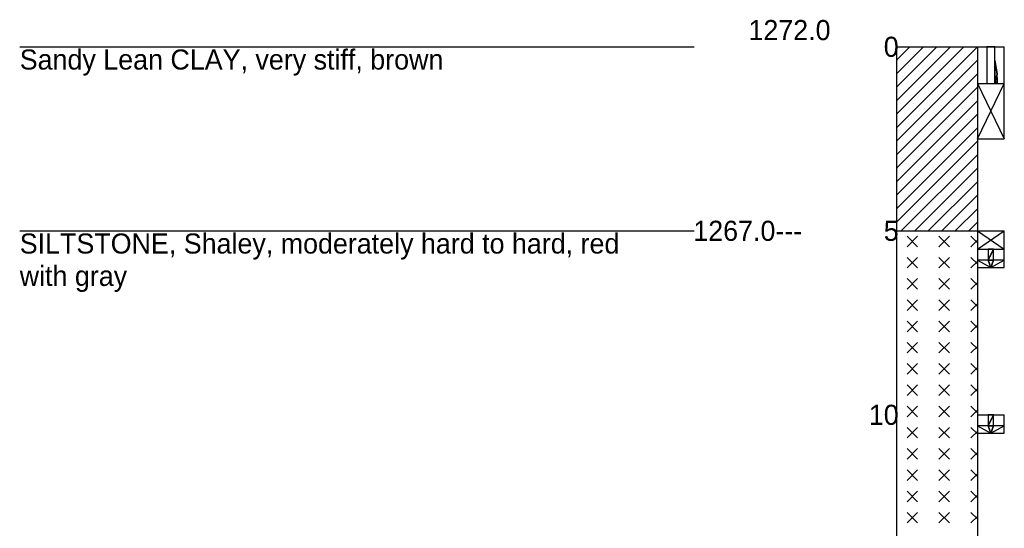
# Model space of a CAD drawing. Extents: x 2150161.5 to 2150203.1, y 143779.5 to 143868.5.
# Drawn here: x 2150186.76 to 2150192.84, y 143852.47 to 143855.61 of the extents above; entities that cross this region are included whole.
import ezdxf

# ---------------------------------------------------------------- set-up
doc = ezdxf.new("R2010")
doc.units = 0
doc.layers.add('Default', color=7, linetype='Continuous')

# ---------------------------------------------------------------- blocks, each defined once
blk = doc.blocks.new('POINT_DISPLAY')
at = {"layer": 'Default'}
blk.add_line((0, 0), (0, 0), dxfattribs=at)

msp = doc.modelspace()

# ---------------------------------------------------------------- linework, layer by layer
at = {"layer": 'Default'}
for points in [[(2150186.7605, 143855.4435), (2150190.9272, 143855.4435)], [(2150192.1772, 143855.3602), (2150192.2605, 143855.4435)], [(2150192.1772, 143855.2768), (2150192.3438, 143855.4435)], [(2150192.1772, 143855.1935), (2150192.4272, 143855.4435)], [(2150192.1772, 143855.1102), (2150192.5105, 143855.4435)], [(2150192.1772, 143855.0268), (2150192.5938, 143855.4435)], [(2150192.1772, 143854.9435), (2150192.6772, 143855.4435)], [(2150192.1772, 143855.4435), (2150192.1772, 143843.2844)], [(2150192.1772, 143855.4435), (2150192.6772, 143855.4435)], [(2150192.6772, 143855.4435), (2150192.8438, 143855.4435)], [(2150192.6772, 143855.4435), (2150192.6772, 143843.2844)], [(2150192.8438, 143855.2162), (2150192.8438, 143855.4435)], [(2150192.1772, 143854.8602), (2150192.6772, 143855.3602)], [(2150192.1772, 143854.7768), (2150192.6772, 143855.2768)], [(2150192.1772, 143854.6935), (2150192.6772, 143855.1935)], [(2150192.6772, 143855.2162), (2150192.8438, 143855.2162)], [(2150192.6772, 143855.2162), (2150192.8438, 143854.8753)], [(2150192.6772, 143854.8753), (2150192.8438, 143855.2162)], [(2150192.6772, 143855.2162), (2150192.8438, 143855.2162)], [(2150192.8438, 143854.8753), (2150192.8438, 143855.2162)], [(2150192.1772, 143854.6102), (2150192.6772, 143855.1102)], [(2150192.1772, 143854.5268), (2150192.6772, 143855.0268)], [(2150192.1772, 143854.4435), (2150192.6772, 143854.9435)], [(2150192.1772, 143854.3602), (2150192.6772, 143854.8602)], [(2150192.6772, 143854.8753), (2150192.8438, 143854.8753)], [(2150192.2075, 143854.3071), (2150192.6772, 143854.7768)], [(2150192.2908, 143854.3071), (2150192.6772, 143854.6935)], [(2150192.3741, 143854.3071), (2150192.6772, 143854.6102)], [(2150192.4575, 143854.3071), (2150192.6772, 143854.5268)], [(2150192.5408, 143854.3071), (2150192.6772, 143854.4435)], [(2150192.6241, 143854.3071), (2150192.6772, 143854.3602)], [(2150186.7605, 143854.3071), (2150190.9272, 143854.3071)], [(2150192.1772, 143854.3071), (2150192.6772, 143854.3071)], [(2150192.3084, 143854.2743), (2150192.2428, 143854.2087)], [(2150192.2428, 143854.2743), (2150192.3084, 143854.2087)], [(2150192.5053, 143854.2743), (2150192.4396, 143854.2087)], [(2150192.4396, 143854.2743), (2150192.5053, 143854.2087)], [(2150192.6365, 143854.2743), (2150192.6772, 143854.2337)], [(2150192.6772, 143854.3071), (2150192.8438, 143854.1935)], [(2150192.6772, 143854.1935), (2150192.8438, 143854.3071)], [(2150192.6772, 143854.3071), (2150192.8438, 143854.3071)], [(2150192.8438, 143854.1935), (2150192.8438, 143854.3071)], [(2150192.6772, 143854.2494), (2150192.6365, 143854.2087)], [(2150192.6772, 143854.1935), (2150192.8438, 143854.1935)], [(2150192.6772, 143854.1935), (2150192.8438, 143854.1935)], [(2150192.8438, 143854.0799), (2150192.8438, 143854.1935)], [(2150192.3084, 143854.1431), (2150192.2428, 143854.0775)], [(2150192.2428, 143854.1431), (2150192.3084, 143854.0775)], [(2150192.5053, 143854.1431), (2150192.4396, 143854.0775)], [(2150192.4396, 143854.1431), (2150192.5053, 143854.0775)], [(2150192.6365, 143854.1431), (2150192.6772, 143854.1024)], [(2150192.6772, 143854.1182), (2150192.6365, 143854.0775)], [(2150192.6772, 143854.0799), (2150192.8438, 143854.0799)], [(2150192.3084, 143854.0119), (2150192.2428, 143853.9463)], [(2150192.2428, 143854.0119), (2150192.3084, 143853.9463)], [(2150192.5053, 143854.0119), (2150192.4396, 143853.9463)], [(2150192.4396, 143854.0119), (2150192.5053, 143853.9463)], [(2150192.6365, 143854.0119), (2150192.6772, 143853.9712)], [(2150192.6772, 143853.9869), (2150192.6365, 143853.9463)], [(2150192.3084, 143853.8806), (2150192.2428, 143853.815)], [(2150192.2428, 143853.8806), (2150192.3084, 143853.815)], [(2150192.5053, 143853.8806), (2150192.4396, 143853.815)], [(2150192.4396, 143853.8806), (2150192.5053, 143853.815)], [(2150192.6365, 143853.8806), (2150192.6772, 143853.84)], [(2150192.6772, 143853.8557), (2150192.6365, 143853.815)], [(2150192.3084, 143853.7494), (2150192.2428, 143853.6838)], [(2150192.2428, 143853.7494), (2150192.3084, 143853.6838)], [(2150192.5053, 143853.7494), (2150192.4396, 143853.6838)], [(2150192.4396, 143853.7494), (2150192.5053, 143853.6838)], [(2150192.6365, 143853.7494), (2150192.6772, 143853.7087)], [(2150192.6772, 143853.7245), (2150192.6365, 143853.6838)], [(2150192.3084, 143853.6182), (2150192.2428, 143853.5526)], [(2150192.2428, 143853.6182), (2150192.3084, 143853.5526)], [(2150192.5053, 143853.6182), (2150192.4396, 143853.5526)], [(2150192.4396, 143853.6182), (2150192.5053, 143853.5526)], [(2150192.6365, 143853.6182), (2150192.6772, 143853.5775)], [(2150192.6772, 143853.5932), (2150192.6365, 143853.5526)], [(2150192.3084, 143853.4869), (2150192.2428, 143853.4213)], [(2150192.2428, 143853.4869), (2150192.3084, 143853.4213)], [(2150192.5053, 143853.4869), (2150192.4396, 143853.4213)], [(2150192.4396, 143853.4869), (2150192.5053, 143853.4213)], [(2150192.6365, 143853.4869), (2150192.6772, 143853.4463)], [(2150192.6772, 143853.462), (2150192.6365, 143853.4213)], [(2150192.3084, 143853.3557), (2150192.2428, 143853.2901)], [(2150192.2428, 143853.3557), (2150192.3084, 143853.2901)], [(2150192.5053, 143853.3557), (2150192.4396, 143853.2901)], [(2150192.4396, 143853.3557), (2150192.5053, 143853.2901)], [(2150192.6365, 143853.3557), (2150192.6772, 143853.315)], [(2150192.6772, 143853.3308), (2150192.6365, 143853.2901)], [(2150192.3084, 143853.2245), (2150192.2428, 143853.1589)], [(2150192.2428, 143853.2245), (2150192.3084, 143853.1589)], [(2150192.5053, 143853.2245), (2150192.4396, 143853.1589)], [(2150192.4396, 143853.2245), (2150192.5053, 143853.1589)], [(2150192.6365, 143853.2245), (2150192.6772, 143853.1838)], [(2150192.6772, 143853.1995), (2150192.6365, 143853.1589)], [(2150192.6772, 143853.1708), (2150192.8438, 143853.1708)], [(2150192.8438, 143853.0572), (2150192.8438, 143853.1708)], [(2150192.3084, 143853.0932), (2150192.2428, 143853.0276)], [(2150192.2428, 143853.0932), (2150192.3084, 143853.0276)], [(2150192.5053, 143853.0932), (2150192.4396, 143853.0276)], [(2150192.4396, 143853.0932), (2150192.5053, 143853.0276)], [(2150192.6365, 143853.0932), (2150192.6772, 143853.0526)], [(2150192.6772, 143853.0683), (2150192.6365, 143853.0276)], [(2150192.6772, 143853.0572), (2150192.8438, 143853.0572)], [(2150192.3084, 143852.962), (2150192.2428, 143852.8964)], [(2150192.2428, 143852.962), (2150192.3084, 143852.8964)], [(2150192.5053, 143852.962), (2150192.4396, 143852.8964)], [(2150192.4396, 143852.962), (2150192.5053, 143852.8964)], [(2150192.6365, 143852.962), (2150192.6772, 143852.9213)], [(2150192.6772, 143852.9371), (2150192.6365, 143852.8964)], [(2150192.3084, 143852.8308), (2150192.2428, 143852.7652)], [(2150192.2428, 143852.8308), (2150192.3084, 143852.7652)], [(2150192.5053, 143852.8308), (2150192.4396, 143852.7652)], [(2150192.4396, 143852.8308), (2150192.5053, 143852.7652)], [(2150192.6365, 143852.8308), (2150192.6772, 143852.7901)], [(2150192.6772, 143852.8058), (2150192.6365, 143852.7652)], [(2150192.3084, 143852.6995), (2150192.2428, 143852.6339)], [(2150192.2428, 143852.6995), (2150192.3084, 143852.6339)], [(2150192.5053, 143852.6995), (2150192.4396, 143852.6339)], [(2150192.4396, 143852.6995), (2150192.5053, 143852.6339)], [(2150192.6365, 143852.6995), (2150192.6772, 143852.6589)], [(2150192.6772, 143852.6746), (2150192.6365, 143852.6339)], [(2150192.3084, 143852.5683), (2150192.2428, 143852.5027)], [(2150192.2428, 143852.5683), (2150192.3084, 143852.5027)], [(2150192.5053, 143852.5683), (2150192.4396, 143852.5027)], [(2150192.4396, 143852.5683), (2150192.5053, 143852.5027)], [(2150192.6365, 143852.5683), (2150192.6772, 143852.5276)], [(2150192.6772, 143852.5434), (2150192.6365, 143852.5027)]]:
    msp.add_lwpolyline(points, dxfattribs=at)
for points in [[(2150192.7355, 143855.4435), (2150192.7355, 143855.2162), (2150192.7855, 143855.2162), (2150192.7855, 143855.4435)], [(2150192.7855, 143855.3585), (2150192.7855, 143855.2162), (2150192.8002, 143855.2768), (2150192.7855, 143855.3585)], [(2150192.7855, 143855.3585), (2150192.8002, 143855.2768), (2150192.7942, 143855.3185), (2150192.7855, 143855.3585)], [(2150192.7855, 143855.2162), (2150192.8022, 143855.2352), (2150192.8002, 143855.2768), (2150192.7855, 143855.2162)], [(2150192.7855, 143855.2162), (2150192.8013, 143855.2162), (2150192.8022, 143855.2352), (2150192.7855, 143855.2162)], [(2150192.7438, 143854.1253), (2150192.7772, 143854.1253), (2150192.7772, 143854.1935), (2150192.7438, 143854.1253)], [(2150192.7438, 143854.1253), (2150192.7772, 143854.1935), (2150192.7438, 143854.1935), (2150192.7438, 143854.1253)], [(2150192.7438, 143854.1253), (2150192.6772, 143854.1253), (2150192.7605, 143854.0799), (2150192.7438, 143854.1253)], [(2150192.7438, 143854.1253), (2150192.7605, 143854.0799), (2150192.7772, 143854.1253), (2150192.7438, 143854.1253)], [(2150192.7605, 143854.0799), (2150192.8438, 143854.1253), (2150192.7772, 143854.1253), (2150192.7605, 143854.0799)], [(2150192.7438, 143853.1026), (2150192.7772, 143853.1026), (2150192.7772, 143853.1708), (2150192.7438, 143853.1026)], [(2150192.7438, 143853.1026), (2150192.7772, 143853.1708), (2150192.7438, 143853.1708), (2150192.7438, 143853.1026)], [(2150192.7438, 143853.1026), (2150192.6772, 143853.1026), (2150192.7605, 143853.0572), (2150192.7438, 143853.1026)], [(2150192.7438, 143853.1026), (2150192.7605, 143853.0572), (2150192.7772, 143853.1026), (2150192.7438, 143853.1026)], [(2150192.7605, 143853.0572), (2150192.8438, 143853.1026), (2150192.7772, 143853.1026), (2150192.7605, 143853.0572)]]:
    msp.add_lwpolyline(points, close=True, dxfattribs=at)

# ---------------------------------------------------------------- block references
at = {"layer": 'Default', "xscale": 0.39369999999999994, "yscale": 0.3936999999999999}
for p in [(2150192.2163, 143855.4268), (2150192.383, 143855.4268), (2150192.283, 143855.3935), (2150192.4059, 143855.3632), (2150192.483, 143855.3935), (2150192.6027, 143855.4102), (2150192.183, 143855.3602), (2150192.2497, 143855.3268), (2150192.4497, 143855.3268), (2150192.5497, 143855.3268), (2150192.6497, 143855.3602), (2150192.2163, 143855.2602), (2150192.3163, 143855.2935), (2150192.4665, 143855.2511), (2150192.6163, 143855.2602), (2150192.2497, 143855.1935), (2150192.383, 143855.2268), (2150192.483, 143855.1935), (2150192.183, 143855.1268), (2150192.3163, 143855.1602), (2150192.4014, 143855.1496), (2150192.6012, 143855.1753), (2150192.6497, 143855.1268), (2150192.283, 143855.0935), (2150192.3497, 143855.0602), (2150192.4529, 143855.0799), (2150192.5163, 143855.0935), (2150192.583, 143855.0602), (2150192.4163, 143855.0268), (2150192.2497, 143854.9935), (2150192.383, 143854.9602), (2150192.4953, 143854.9935), (2150192.6163, 143854.9935), (2150192.183, 143854.9268), (2150192.283, 143854.8935), (2150192.4497, 143854.8935), (2150192.5497, 143854.9268), (2150192.2163, 143854.8602), (2150192.4163, 143854.8268), (2150192.6163, 143854.8602), (2150192.2163, 143854.7602), (2150192.383, 143854.7602), (2150192.5163, 143854.7935), (2150192.183, 143854.6935), (2150192.283, 143854.7268), (2150192.4059, 143854.6965), (2150192.483, 143854.7268), (2150192.6027, 143854.7435), (2150192.6497, 143854.6935), (2150192.2497, 143854.6602), (2150192.4497, 143854.6602), (2150192.5497, 143854.6602), (2150192.2163, 143854.5935), (2150192.3163, 143854.6268), (2150192.4665, 143854.5844), (2150192.6163, 143854.5935), (2150192.2497, 143854.5268), (2150192.383, 143854.5602), (2150192.483, 143854.5268), (2150192.183, 143854.4602), (2150192.3163, 143854.4935), (2150192.4014, 143854.4829), (2150192.6012, 143854.5087), (2150192.6497, 143854.4602), (2150192.283, 143854.4268), (2150192.3497, 143854.3935), (2150192.4529, 143854.4132), (2150192.5163, 143854.4268), (2150192.583, 143854.3935), (2150192.4163, 143854.3602), (2150192.2497, 143854.3268), (2150192.4953, 143854.3268), (2150192.6163, 143854.3268)]:
    msp.add_blockref('POINT_DISPLAY', p, dxfattribs=at)

# ---------------------------------------------------------------- texts
at = {"layer": 'Default'}
for s, p in [('1272.0', (2150191.2631, 143855.4848)), ('0', (2150192.0989, 143855.3815)), ('Sandy Lean CLAY, very stiff, brown', (2150186.7605, 143855.3028)), ('1267.0---', (2150190.9223, 143854.2451)), ('5', (2150192.0989, 143854.2451)), ('SILTSTONE, Shaley, moderately hard to hard, red', (2150186.7605, 143854.1665)), ('with gray', (2150186.7605, 143853.9665)), ('10', (2150192.0068, 143853.1088))]:
    msp.add_text(s, height=0.124, dxfattribs=at).set_placement(p)

doc.saveas('drawing.dxf')
